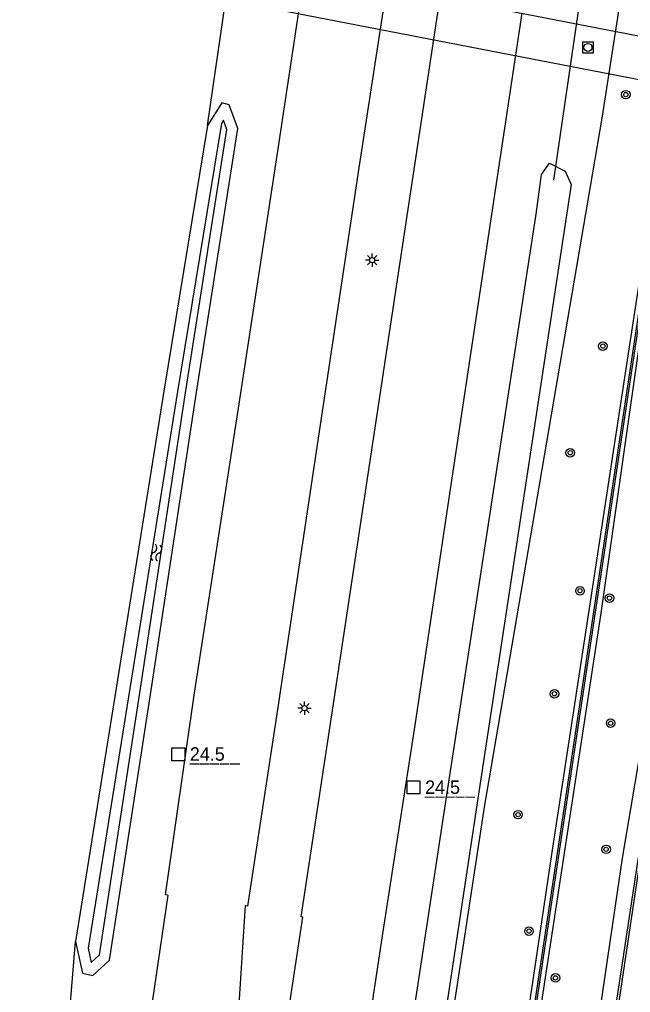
# Model space of a CAD drawing. Extents: x 124000 to 128010, y 398999 to 403000.
# Drawn here: x 126267.4 to 126324.4, y 399560.1 to 399650.9 of the extents above; entities that cross this region are included whole.
import ezdxf

# ---------------------------------------------------------------- set-up
doc = ezdxf.new("R2010")
doc.units = 0
for name, color, linetype in [('gg-afsc-geluidsscherm', 7, 'Continuous'), ('gg-knt-BGT kruinlijn', 7, 'Continuous'), ('gg-knt-bovenkant onderkant talud', 7, 'Continuous'), ('gg-knt-verharding', 7, 'Continuous'), ('gg-kntw-bovenkant insteek waterloop', 7, 'Continuous'), ('gg-kntw-waterlijn', 7, 'Continuous'), ('gg-kwrk-duiker nz buis', 7, 'Continuous'), ('gg-kwrk-duiker nz vlak', 7, 'Continuous'), ('gt-anno-nummer hm paal', 7, 'Continuous'), ('gt-grn-groengrens', 7, 'Continuous'), ('gt-symb-boom', 7, 'Continuous'), ('gt-symb-hm paal', 7, 'Continuous'), ('gt-symb-lichtmast', 7, 'Continuous'), ('gt-symb-rioolschacht', 7, 'Continuous'), ('gt-symb-watersymbool', 7, 'Continuous')]:
    doc.layers.add(name, color=color, linetype=linetype)

# ---------------------------------------------------------------- blocks, each defined once
blk = doc.blocks.new('gt0-BOOM')
at = {"layer": 'gt-symb-boom'}
for radius in [0.4, 0.2]:
    blk.add_circle((0, 0), radius, dxfattribs=at)
blk = doc.blocks.new('gt0-RS')
at = {"layer": 'gt-symb-rioolschacht'}
blk.add_lwpolyline([(-0.5, -0.5), (0.5, -0.5), (0.5, 0.5), (-0.5, 0.5)], close=True, dxfattribs=at)
blk.add_circle((0, 0), 0.375, dxfattribs=at)
blk = doc.blocks.new('gt0-WA')
at = {"layer": 'gt-symb-watersymbool'}
for centre, start, end in [((-0.323, 0.022), 28.07249, 151.92751), ((0.427, 0.422), 208.07248, 331.92751), ((-0.323, -0.428), 28.07249, 151.92751), ((0.427, -0.028), 208.07248, 331.92751)]:
    blk.add_arc(centre, 0.425, start, end, dxfattribs=at)
blk = doc.blocks.new('gt0-HMpaal')
at = {"layer": 'gt-symb-hm paal'}
blk.add_lwpolyline([(-0.6, 0.6), (0.6, 0.6), (0.6, -0.6), (-0.6, -0.6)], close=True, dxfattribs=at)
blk = doc.blocks.new('gt0-LMAST')
at = {"layer": 'gt-symb-lichtmast'}
for p, q in [((-0.182, 0.173), (-0.447, 0.438)), ((-0.005, 0.246), (-0.005, 0.621)), ((0.172, 0.173), (0.437, 0.438)), ((-0.255, -0.004), (-0.63, -0.004)), ((-0.182, -0.181), (-0.447, -0.446)), ((-0.005, -0.254), (-0.005, -0.629)), ((0.437, -0.446), (0.172, -0.181)), ((0.245, -0.004), (0.62, -0.004))]:
    blk.add_line(p, q, dxfattribs=at)
blk.add_circle((-0.005, -0.004), 0.25, dxfattribs=at)

msp = doc.modelspace()

# ---------------------------------------------------------------- linework, layer by layer
at = {"layer": 'gg-afsc-geluidsscherm'}
for points in [[(126433.522, 399396.193), (126294.266, 399417.89), (126294.312, 399418.568), (126384.69, 400018.495), (126392.393, 400081.874), (126401.389, 400173.179), (126405.812, 400237.067), (126415.183, 400254.387), (126416.933, 400270.191), (126421.505, 400378.061), (126422.448, 400394.046), (126423.962, 400411.149), (126518.093, 400411.476), (126531.613, 400399.449), (126531.513, 400399.337)], [(126433.522, 399396.193), (126433.545, 399396.341), (126294.438, 399418.015), (126294.46, 399418.546), (126384.838, 400018.472), (126392.542, 400081.856), (126401.538, 400173.164), (126405.962, 400237.057), (126415.315, 400254.315), (126417.082, 400270.175), (126421.655, 400378.055), (126422.598, 400394.037), (126424.098, 400410.986), (126518.093, 400411.326), (126531.513, 400399.337)]]:
    msp.add_lwpolyline(points, dxfattribs=at)
at = {"layer": 'gg-knt-BGT kruinlijn'}
for points in [[(126300.242, 399460.061), (126317.155, 399573.618), (126327.853, 399643.472), (126345.991, 399764.256), (126377.209, 399971.201), (126384.168, 400018.601), (126391.597, 400079.17), (126401.015, 400171.969), (126405.272, 400237.075), (126405.836, 400239.447)], [(126332.168, 399665.424), (126332.505, 399664.403), (126326.997, 399627.412), (126326.354, 399625.57), (126325.748, 399624.249), (126321.63, 399595.513), (126311.054, 399526.142)]]:
    msp.add_lwpolyline(points, dxfattribs=at)
at = {"layer": 'gg-knt-bovenkant onderkant talud'}
msp.add_lwpolyline([(126293.229, 399462.196), (126310.804, 399577.419), (126321.785, 399641.664), (126324.83, 399661.281), (126341.384, 399769.192), (126355.148, 399863.606), (126371.991, 399972.892), (126378.989, 400019.753), (126385.648, 400077.466), (126395.494, 400171.208), (126398.482, 400218.678), (126399.195, 400237.176), (126399.855, 400244.875), (126401.075, 400247.387), (126403.954, 400253.411), (126406.57, 400258.304), (126407.848, 400260.608), (126408.109, 400271.651), (126414.004, 400375.395), (126416.291, 400410.556)], dxfattribs=at)
at = {"layer": 'gg-knt-verharding'}
for p, q in [((126306.074, 399649.015), (126306.668, 399652.931)), ((126313.707, 399647.545), (126314.299, 399651.457)), ((126313.113, 399643.62), (126313.707, 399647.545)), ((126288.482, 399568.234), (126287.194, 399548.857))]:
    msp.add_line(p, q, dxfattribs=at)
for points in [[(126281.268, 399569.207), (126281.051, 399569.25), (126283.729, 399587.86), (126287.911, 399615.007), (126291.464, 399638.179), (126299.727, 399693.107), (126303.929, 399720.402), (126307.85, 399746.666), (126311.948, 399773.59), (126316.059, 399800.688), (126320.368, 399829.194), (126324.228, 399854.576)], [(126331.92, 399853.409), (126327.954, 399827.368), (126323.796, 399799.859), (126319.554, 399771.955), (126315.486, 399744.891), (126311.525, 399718.81), (126307.36, 399691.657), (126303.905, 399668.386), (126299.079, 399637.02), (126295.467, 399613.062), (126291.549, 399586.917), (126288.696, 399568.194), (126288.482, 399568.234)], [(126291.002, 399548.28), (126293.861, 399567.154), (126293.699, 399567.18), (126296.564, 399586.022), (126306.074, 399649.015)], [(126278.26, 399414.971), (126278.518, 399416.766), (126278.741, 399416.761), (126283.335, 399446.45), (126301.283, 399565.425), (126304.343, 399585.077), (126308.232, 399611.211), (126313.113, 399643.62)], [(126325.656, 399572.157), (126325.266, 399572.222), (126318.447, 399526.506)], [(126281.268, 399569.207), (126279.604, 399557.956), (126271.321, 399503.46), (126262.868, 399448.022), (126260.11, 399430.241), (126257.35, 399412.038)]]:
    msp.add_lwpolyline(points, dxfattribs=at)
at = {"layer": 'gg-kntw-bovenkant insteek waterloop'}
for points in [[(126272.657, 399564.903), (126273.304, 399561.928), (126274.252, 399561.711), (126275.832, 399563.145), (126279.694, 399588.339), (126283.894, 399615.894), (126287.794, 399640.7), (126286.989, 399642.901), (126286.289, 399643.1), (126284.969, 399640.979)], [(126284.969, 399640.979), (126280.921, 399616.38), (126272.657, 399564.903)], [(126289.731, 399462.927), (126307.243, 399578.341), (126315.618, 399632.704), (126316.119, 399636.407), (126316.862, 399637.458), (126318.32, 399636.714), (126318.891, 399635.479), (126310.066, 399577.615), (126292.671, 399462.253)], [(126332.067, 399624.359), (126332.877, 399624.714), (126333.35, 399624.528), (126333.444, 399623.719), (126328.302, 399591.015), (126325.077, 399572.307), (126318.09, 399526.371)], [(126440.492, 399390.061), (126441.486, 399392.554), (126442.659, 399396.473), (126442.835, 399398.872), (126441.861, 399400.992), (126440.956, 399402.498), (126438.557, 399403.971), (126434.182, 399404.897), (126399.798, 399410.376), (126389.452, 399411.435), (126378.388, 399413.262), (126360.318, 399415.739), (126304.318, 399423.704), (126302.171, 399424.161), (126301.705, 399425.225), (126307.402, 399462.554), (126311.526, 399492.391), (126316.901, 399526.627), (126323.667, 399572.649), (126326.816, 399591.238)]]:
    msp.add_lwpolyline(points, dxfattribs=at)
at = {"layer": 'gg-kntw-waterlijn'}
msp.add_lwpolyline([(126273.82, 399564.261), (126274.109, 399562.932), (126274.897, 399563.647), (126278.705, 399588.49), (126282.906, 399616.047), (126286.766, 399640.6), (126286.449, 399641.465), (126286.268, 399641.173), (126282.155, 399616.179), (126273.82, 399564.261)], dxfattribs=at)
at = {"layer": 'gg-kwrk-duiker nz buis'}
msp.add_line((126317.255, 399635.883), (126320.911, 399660.819), dxfattribs=at)
at = {"layer": 'gg-kwrk-duiker nz vlak'}
msp.add_line((126268.817, 399656.188), (126335.256, 399643.319), dxfattribs=at)
msp.add_lwpolyline([(126336.066, 399647.185), (126269.604, 399660.093), (126268.817, 399656.188)], dxfattribs=at)
at = {"layer": 'gt-grn-groengrens'}
for p, q in [((126284.969, 399640.979), (126286.66, 399652.753)), ((126271.886, 399555.538), (126272.657, 399564.903))]:
    msp.add_line(p, q, dxfattribs=at)

# ---------------------------------------------------------------- block references
at = {"layer": 'gt-symb-boom'}
for p in [(126323.976, 399643.851), (126321.836, 399620.402), (126318.796, 399610.46), (126319.702, 399597.597), (126322.45, 399596.914), (126317.321, 399587.987), (126322.559, 399585.24), (126313.923, 399576.718), (126322.133, 399573.483), (126314.944, 399565.86), (126317.412, 399561.499)]:
    msp.add_blockref('gt0-BOOM', p, dxfattribs=at)
at = {"layer": 'gt-symb-hm paal'}
for p in [(126282.233, 399582.351), (126304.174, 399579.258)]:
    msp.add_blockref('gt0-HMpaal', p, dxfattribs=at)
at = {"layer": 'gt-symb-lichtmast'}
for p in [(126300.325, 399628.423), (126294.011, 399586.653)]:
    msp.add_blockref('gt0-LMAST', p, dxfattribs=at)
at = {"layer": 'gt-symb-rioolschacht'}
msp.add_blockref('gt0-RS', (126320.446, 399648.253), dxfattribs=at)
at = {"layer": 'gt-symb-watersymbool', "rotation": 81.1405706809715}
msp.add_blockref('gt0-WA', (126280.175, 399601.087), dxfattribs=at)

# ---------------------------------------------------------------- texts
at = {"layer": 'gt-anno-nummer hm paal'}
for p in [(126283.314, 399581.747), (126305.255, 399578.654)]:
    msp.add_text('24.5', height=1.25, dxfattribs=at).set_placement(p)
at = {"layer": 'gt-symb-hm paal'}
for p in [(126283.314, 399581.747), (126305.255, 399578.654)]:
    msp.add_text('_____', height=1.25, dxfattribs=at).set_placement(p)

doc.saveas('drawing.dxf')
